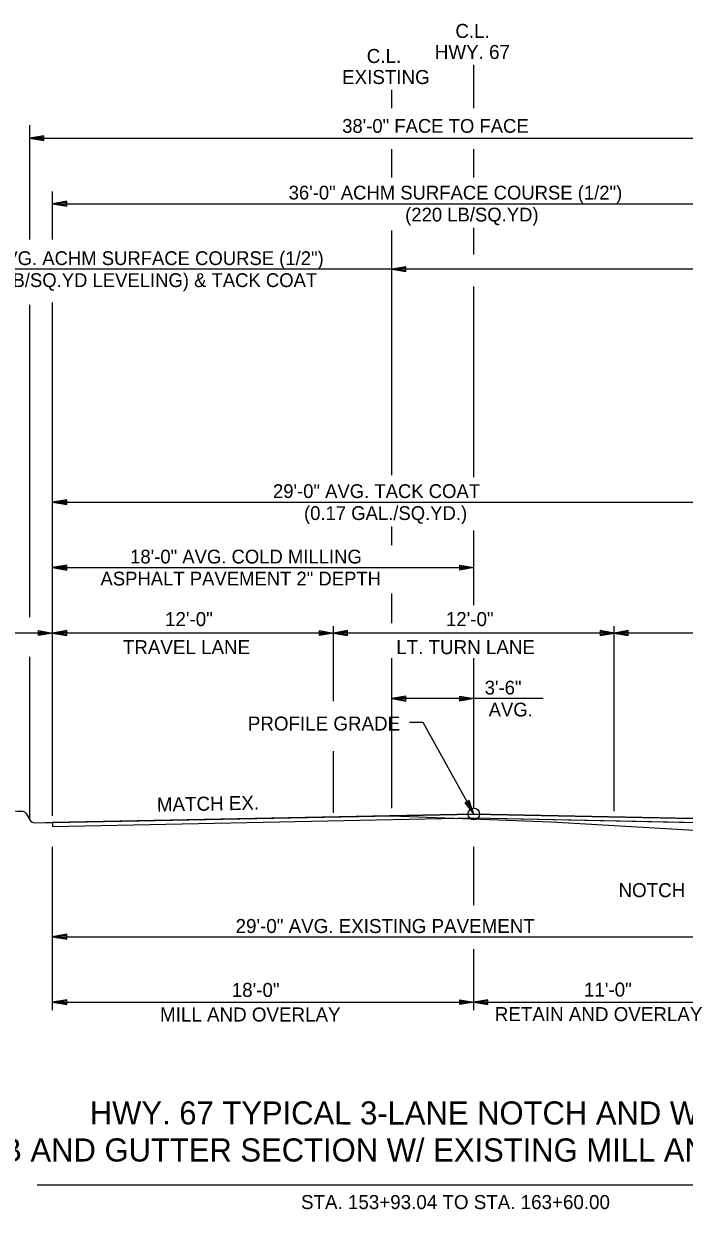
# Model space of a CAD drawing. Extents: x 1001270 to 1003428, y 1840152 to 1842912.
# Drawn here: x 1001851 to 1001879.2, y 1841963.7 to 1842014.4 of the extents above; entities that cross this region are included whole.
import ezdxf

# ---------------------------------------------------------------- set-up
doc = ezdxf.new("R2010")
doc.units = 0
doc.layers.add('19', color=7, linetype='Continuous')

msp = doc.modelspace()

# ---------------------------------------------------------------- linework, layer by layer
at = {"layer": '19'}
for p, q in [((1001870.197, 1842010.769), (1001870.197, 1842012.627)), ((1001866.697, 1842010.769), (1001866.697, 1842011.555)), ((1001851.226, 1842005.155), (1001851.226, 1842010.042)), ((1001851.826, 1842009.593), (1001851.226, 1842009.488)), ((1001851.226, 1842009.488), (1001889.198, 1842009.488)), ((1001851.226, 1842009.488), (1001851.826, 1842009.383)), ((1001851.826, 1842009.538), (1001851.386, 1842009.503)), ((1001851.386, 1842009.473), (1001851.826, 1842009.433)), ((1001851.826, 1842009.383), (1001851.826, 1842009.593)), ((1001866.697, 1842007.811), (1001866.697, 1842009.019)), ((1001870.197, 1842007.811), (1001870.197, 1842009.019)), ((1001852.197, 1842005.156), (1001852.197, 1842007.213)), ((1001852.797, 1842006.793), (1001852.197, 1842006.688)), ((1001852.197, 1842006.688), (1001852.797, 1842006.583)), ((1001852.197, 1842006.688), (1001888.197, 1842006.688)), ((1001852.797, 1842006.738), (1001852.357, 1842006.703)), ((1001852.357, 1842006.673), (1001852.797, 1842006.633)), ((1001852.797, 1842006.583), (1001852.797, 1842006.793)), ((1001866.697, 1841995.07), (1001866.697, 1842005.54)), ((1001870.197, 1842004.515), (1001870.197, 1842005.648)), ((1001891.194, 1842003.888), (1001846.632, 1842003.888)), ((1001867.297, 1842003.993), (1001866.697, 1842003.888)), ((1001866.697, 1842003.888), (1001867.297, 1842003.783)), ((1001867.297, 1842003.938), (1001866.857, 1842003.903)), ((1001866.857, 1842003.873), (1001867.297, 1842003.833)), ((1001867.297, 1842003.783), (1001867.297, 1842003.993)), ((1001870.197, 1841994.997), (1001870.197, 1842003.144)), ((1001851.226, 1841988.998), (1001851.226, 1842002.359)), ((1001852.197, 1841988.621), (1001852.197, 1842002.458)), ((1001852.797, 1841994.026), (1001852.197, 1841993.921)), ((1001852.197, 1841993.921), (1001881.194, 1841993.921)), ((1001852.197, 1841993.921), (1001852.797, 1841993.816)), ((1001852.797, 1841993.971), (1001852.357, 1841993.936)), ((1001852.357, 1841993.906), (1001852.797, 1841993.866)), ((1001852.797, 1841993.816), (1001852.797, 1841994.026)), ((1001866.697, 1841992.086), (1001866.697, 1841992.887)), ((1001870.197, 1841989.519), (1001870.197, 1841992.705)), ((1001852.797, 1841991.226), (1001852.197, 1841991.121)), ((1001852.797, 1841991.171), (1001852.357, 1841991.136)), ((1001852.797, 1841991.016), (1001852.797, 1841991.226)), ((1001869.597, 1841991.016), (1001869.597, 1841991.226)), ((1001869.597, 1841991.226), (1001870.197, 1841991.121)), ((1001869.597, 1841991.171), (1001870.037, 1841991.136)), ((1001852.197, 1841991.121), (1001870.197, 1841991.121)), ((1001852.197, 1841991.121), (1001852.797, 1841991.016)), ((1001852.357, 1841991.106), (1001852.797, 1841991.066)), ((1001870.197, 1841991.121), (1001869.597, 1841991.016)), ((1001870.037, 1841991.106), (1001869.597, 1841991.066)), ((1001866.697, 1841988.741), (1001866.697, 1841990.013)), ((1001853.879, 1841988.321), (1001842.7, 1841988.321)), ((1001851.597, 1841988.216), (1001851.597, 1841988.426)), ((1001851.597, 1841988.426), (1001852.197, 1841988.321)), ((1001851.597, 1841988.371), (1001852.037, 1841988.336)), ((1001852.197, 1841988.321), (1001851.597, 1841988.216)), ((1001852.037, 1841988.306), (1001851.597, 1841988.266)), ((1001852.197, 1841980.507), (1001852.197, 1841988.621)), ((1001852.797, 1841988.426), (1001852.197, 1841988.321)), ((1001864.197, 1841988.321), (1001852.197, 1841988.321)), ((1001852.197, 1841988.321), (1001852.797, 1841988.216)), ((1001852.797, 1841988.371), (1001852.357, 1841988.336)), ((1001852.357, 1841988.306), (1001852.797, 1841988.266)), ((1001852.797, 1841988.216), (1001852.797, 1841988.426)), ((1001863.597, 1841988.216), (1001863.597, 1841988.426)), ((1001863.597, 1841988.426), (1001864.197, 1841988.321)), ((1001863.597, 1841988.371), (1001864.037, 1841988.336)), ((1001864.197, 1841988.321), (1001863.597, 1841988.216)), ((1001864.037, 1841988.306), (1001863.597, 1841988.266)), ((1001864.197, 1841985.407), (1001864.197, 1841988.621)), ((1001864.797, 1841988.426), (1001864.197, 1841988.321)), ((1001876.197, 1841988.321), (1001864.197, 1841988.321)), ((1001864.197, 1841988.321), (1001864.797, 1841988.216)), ((1001864.797, 1841988.371), (1001864.357, 1841988.336)), ((1001864.357, 1841988.306), (1001864.797, 1841988.266)), ((1001864.797, 1841988.216), (1001864.797, 1841988.426)), ((1001875.597, 1841988.426), (1001875.597, 1841988.216)), ((1001876.197, 1841988.321), (1001875.597, 1841988.426)), ((1001876.037, 1841988.336), (1001875.597, 1841988.371)), ((1001875.597, 1841988.216), (1001876.197, 1841988.321)), ((1001875.597, 1841988.266), (1001876.037, 1841988.306)), ((1001876.197, 1841980.713), (1001876.197, 1841988.621)), ((1001876.797, 1841988.426), (1001876.197, 1841988.321)), ((1001888.197, 1841988.321), (1001876.197, 1841988.321)), ((1001876.197, 1841988.321), (1001876.797, 1841988.216)), ((1001876.797, 1841988.371), (1001876.357, 1841988.336)), ((1001876.357, 1841988.306), (1001876.797, 1841988.266)), ((1001876.797, 1841988.216), (1001876.797, 1841988.426)), ((1001851.226, 1841980.332), (1001851.226, 1841987.306)), ((1001866.697, 1841980.833), (1001866.697, 1841987.253)), ((1001870.197, 1841980.833), (1001870.197, 1841987.253)), ((1001867.292, 1841985.626), (1001866.692, 1841985.521)), ((1001867.292, 1841985.416), (1001867.292, 1841985.626)), ((1001869.597, 1841985.416), (1001869.597, 1841985.626)), ((1001869.597, 1841985.626), (1001870.197, 1841985.521)), ((1001866.692, 1841985.521), (1001867.292, 1841985.416)), ((1001873.164, 1841985.521), (1001866.697, 1841985.521)), ((1001867.292, 1841985.571), (1001866.852, 1841985.536)), ((1001866.852, 1841985.506), (1001867.292, 1841985.466)), ((1001869.597, 1841985.571), (1001870.037, 1841985.536)), ((1001870.197, 1841985.521), (1001869.597, 1841985.416)), ((1001870.037, 1841985.506), (1001869.597, 1841985.466)), ((1001864.197, 1841980.633), (1001864.197, 1841983.267)), ((1001869.998, 1841981.158), (1001869.816, 1841981.057)), ((1001869.816, 1841981.057), (1001870.197, 1841980.583)), ((1001869.858, 1841981.076), (1001870.106, 1841980.716)), ((1001870.13, 1841980.727), (1001869.954, 1841981.128)), ((1001870.197, 1841980.583), (1001869.998, 1841981.158)), ((1001852.197, 1841980.223), (1001870.197, 1841980.583)), ((1001870.197, 1841980.583), (1001888.197, 1841980.223)), ((1001852.197, 1841980.056), (1001870.197, 1841980.416)), ((1001870.197, 1841980.416), (1001888.197, 1841980.056)), ((1001852.197, 1841972.19), (1001852.197, 1841979.178)), ((1001870.197, 1841976.683), (1001870.197, 1841979.178)), ((1001852.797, 1841975.443), (1001852.197, 1841975.338)), ((1001852.797, 1841975.233), (1001852.797, 1841975.443)), ((1001852.197, 1841975.338), (1001881.179, 1841975.338)), ((1001852.197, 1841975.338), (1001852.797, 1841975.233)), ((1001852.797, 1841975.388), (1001852.357, 1841975.353)), ((1001852.357, 1841975.323), (1001852.797, 1841975.283)), ((1001870.197, 1841972.19), (1001870.197, 1841974.798)), ((1001852.797, 1841972.643), (1001852.197, 1841972.538)), ((1001852.197, 1841972.538), (1001870.197, 1841972.538)), ((1001852.197, 1841972.538), (1001852.797, 1841972.433)), ((1001852.797, 1841972.588), (1001852.357, 1841972.553)), ((1001852.357, 1841972.523), (1001852.797, 1841972.483)), ((1001852.797, 1841972.433), (1001852.797, 1841972.643)), ((1001869.597, 1841972.433), (1001869.597, 1841972.643)), ((1001869.597, 1841972.643), (1001870.197, 1841972.538)), ((1001869.597, 1841972.588), (1001870.037, 1841972.553)), ((1001870.197, 1841972.538), (1001869.597, 1841972.433)), ((1001870.037, 1841972.523), (1001869.597, 1841972.483)), ((1001870.179, 1841972.538), (1001881.179, 1841972.538)), ((1001870.797, 1841972.643), (1001870.197, 1841972.538)), ((1001870.197, 1841972.538), (1001870.797, 1841972.433)), ((1001870.797, 1841972.588), (1001870.357, 1841972.553)), ((1001870.357, 1841972.523), (1001870.797, 1841972.483)), ((1001870.797, 1841972.433), (1001870.797, 1841972.643)), ((1001851.535, 1841964.731), (1001888.921, 1841964.731))]:
    msp.add_line(p, q, dxfattribs=at)
for points in [[(1001867.452, 1841984.515), (1001868.022, 1841984.515), (1001870.197, 1841980.583)], [(1001835.469, 1841983.278), (1001842.7, 1841980.868), (1001850.697, 1841980.708), (1001850.864, 1841980.708), (1001850.928, 1841980.7), (1001850.989, 1841980.674), (1001851.04, 1841980.635), (1001851.08, 1841980.583), (1001851.226, 1841980.332), (1001851.266, 1841980.28), (1001851.32, 1841980.24), (1001851.383, 1841980.215), (1001851.447, 1841980.208), (1001851.913, 1841980.217), (1001852.197, 1841980.223), (1001855.158, 1841980.282), (1001866.695, 1841980.513)], [(1001866.695, 1841980.513), (1001873.496, 1841980.252), (1001880.133, 1841979.869), (1001885.197, 1841979.783), (1001887.878, 1841979.721)]]:
    msp.add_lwpolyline(points, dxfattribs=at)
msp.add_lwpolyline([(1001870.197, 1841980.583), (1001852.197, 1841980.223), (1001852.197, 1841980.056), (1001870.197, 1841980.416), (1001888.197, 1841980.056), (1001888.197, 1841980.223)], close=True, dxfattribs=at)
msp.add_circle((1001870.197, 1841980.583), 0.25, dxfattribs=at)

# ---------------------------------------------------------------- texts
for s, height, p in [('C.L.', 0.6, (1001869.409, 1842013.776)), ('HWY. 67', 0.6, (1001868.531, 1842012.876)), ('C.L.', 0.6, (1001865.623, 1842012.704)), ('EXISTING', 0.6, (1001864.567, 1842011.804)), ('38\'-0" FACE TO FACE', 0.59001, (1001864.57, 1842009.719)), ('36\'-0" ACHM SURFACE COURSE (1/2")', 0.59001, (1001862.283, 1842006.866)), ('(220 LB/SQ.YD)', 0.59001, (1001867.264, 1842005.926)), ('14\'-6" AVG. ACHM SURFACE COURSE (1/2")', 0.59001, (1001847.42, 1842004.062)), ('(VAR. LB/SQ.YD LEVELING) & TACK COAT', 0.59001, (1001847.72, 1842003.122)), ('29\'-0" AVG. TACK COAT', 0.59001, (1001861.614, 1841994.099)), ('(0.17 GAL./SQ.YD.)', 0.59001, (1001862.94, 1841993.159)), ('18\'-0" AVG. COLD MILLING', 0.59001, (1001855.509, 1841991.299)), ('ASPHALT PAVEMENT 2" DEPTH', 0.59001, (1001854.243, 1841990.359)), ('12\'-0"', 0.6, (1001857, 1841988.621)), ('12\'-0"', 0.6, (1001869, 1841988.621)), ('TRAVEL LANE', 0.6, (1001855.197, 1841987.421)), ('LT. TURN LANE', 0.6, (1001866.881, 1841987.421)), ('3\'-6"', 0.59, (1001870.663, 1841985.696)), ('AVG.', 0.59, (1001870.832, 1841984.756)), ('PROFILE GRADE', 0.6, (1001860.539, 1841984.153)), ('NOTCH', 0.6, (1001876.381, 1841977.028))]:
    msp.add_text(s, height=height, dxfattribs=at).set_placement(p)
for s, height, rotation, p in [('MATCH EX.', 0.6, 1.1458, (1001856.658, 1841980.685)), ('29\'-0" AVG. EXISTING PAVEMENT', 0.6, 360, (1001860.016, 1841975.494)), ('18\'-0"', 0.6, 360, (1001859.852, 1841972.76)), ('11\'-0"', 0.6, 360, (1001874.904, 1841972.776)), ('MILL AND OVERLAY', 0.6, 360, (1001856.788, 1841971.71)), ('RETAIN AND OVERLAY', 0.6, 360, (1001871.094, 1841971.726)), ('HWY. 67 TYPICAL 3-LANE NOTCH AND WIDEN ', 0.98999, 359.9954, (1001853.785, 1841967.306)), ('CURB AND GUTTER SECTION W/ EXISTING MILL AND OVERLAY', 0.98999, 359.9954, (1001847.131, 1841965.722)), ('STA. 153+93.04 TO STA. 163+60.00', 0.6, 359.9954, (1001862.812, 1841963.688))]:
    msp.add_text(s, height=height, rotation=rotation, dxfattribs=at).set_placement(p)

doc.saveas('drawing.dxf')
